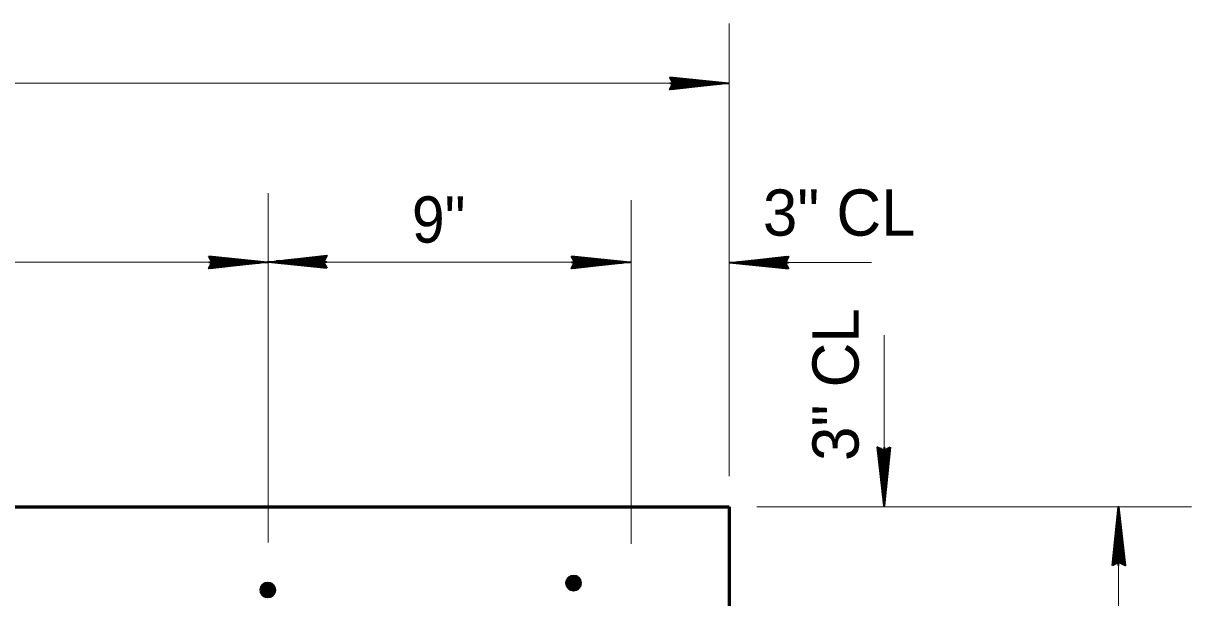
# Model space of a CAD drawing. Extents: x 4.49 to 7.69, y 0.28 to 2.27.
# Drawn here: x 5.3295 to 5.54, y 1.4617 to 1.5652 of the extents above; entities that cross this region are included whole.
import ezdxf
from ezdxf.enums import TextEntityAlignment as Align

# ---------------------------------------------------------------- set-up
doc = ezdxf.new("R2010")
doc.units = 0
doc.header["$LTSCALE"] = 0.0033
doc.layers.add('1', color=7, linetype='Continuous', lineweight=35)

msp = doc.modelspace()

# ---------------------------------------------------------------- linework, layer by layer
at = {"layer": '1', "lineweight": 13}
for p, q in [((5.456667, 1.483583), (5.456667, 1.565167)), ((4.87325, 1.554417), (5.455583, 1.554417)), ((5.373583, 1.471667), (5.373583, 1.534583)), ((5.439, 1.471417), (5.439, 1.533333)), ((4.89, 1.522167), (5.436917, 1.522167)), ((5.466583, 1.522083), (5.482333, 1.522083)), ((5.484583, 1.488167), (5.484583, 1.509)), ((5.461667, 1.478083), (5.54, 1.478083)), ((5.526833, 1.477417), (5.526833, 1.311417))]:
    msp.add_line(p, q, dxfattribs=at)
at = {"layer": '1'}
for p, q in [((5.446, 1.554417), (5.456583, 1.554417)), ((5.446167, 1.55375), (5.4535, 1.5545)), ((5.44625, 1.555417), (5.454083, 1.5545)), ((5.44625, 1.555417), (5.454083, 1.5545)), ((5.44625, 1.555333), (5.454083, 1.5545)), ((5.44625, 1.55525), (5.454083, 1.554417)), ((5.44625, 1.55525), (5.454083, 1.55425)), ((5.44625, 1.553583), (5.453583, 1.554417)), ((5.44625, 1.5535), (5.453583, 1.55425)), ((5.44625, 1.553333), (5.453583, 1.554167)), ((5.362917, 1.522167), (5.3735, 1.522167)), ((5.363083, 1.5215), (5.370417, 1.52225)), ((5.363167, 1.523167), (5.371, 1.52225)), ((5.363167, 1.523167), (5.371, 1.52225)), ((5.363167, 1.523083), (5.371, 1.52225)), ((5.363167, 1.523), (5.371, 1.522167)), ((5.363167, 1.523), (5.371, 1.522)), ((5.363167, 1.521333), (5.3705, 1.522167)), ((5.363167, 1.52125), (5.3705, 1.522)), ((5.384167, 1.522167), (5.373583, 1.522167)), ((5.383917, 1.521333), (5.376083, 1.522333)), ((5.383917, 1.521333), (5.376083, 1.522167)), ((5.383917, 1.521167), (5.376083, 1.522083)), ((5.383917, 1.521167), (5.376083, 1.522083)), ((5.383917, 1.52125), (5.376083, 1.522083)), ((5.383917, 1.52325), (5.376583, 1.522417)), ((5.383917, 1.523083), (5.376583, 1.522333)), ((5.383917, 1.523), (5.376583, 1.522167)), ((5.384, 1.522833), (5.376667, 1.522083)), ((5.42825, 1.522167), (5.438833, 1.522167)), ((5.428417, 1.5215), (5.43575, 1.52225)), ((5.4285, 1.523167), (5.436333, 1.52225)), ((5.4285, 1.523167), (5.436333, 1.52225)), ((5.4285, 1.523083), (5.436333, 1.52225)), ((5.4285, 1.523), (5.436333, 1.522167)), ((5.4285, 1.523), (5.436333, 1.522)), ((5.4285, 1.521333), (5.435833, 1.522167)), ((5.4285, 1.52125), (5.435833, 1.522)), ((5.467333, 1.522), (5.45675, 1.522)), ((5.467083, 1.521167), (5.45925, 1.522167)), ((5.467083, 1.521167), (5.45925, 1.522)), ((5.467083, 1.523083), (5.45975, 1.52225)), ((5.467083, 1.522917), (5.45975, 1.522167)), ((5.467083, 1.522833), (5.45975, 1.522)), ((5.467167, 1.522667), (5.459833, 1.521917)), ((5.363167, 1.521083), (5.3705, 1.521917)), ((5.4285, 1.521083), (5.435833, 1.521917)), ((5.467083, 1.521), (5.45925, 1.521917)), ((5.467083, 1.521), (5.45925, 1.521917)), ((5.467083, 1.521083), (5.45925, 1.521917)), ((5.4835, 1.488583), (5.484333, 1.48125)), ((5.483667, 1.488583), (5.484417, 1.48125)), ((5.48375, 1.488583), (5.484583, 1.48125)), ((5.483917, 1.488667), (5.484667, 1.481333)), ((5.485417, 1.488583), (5.484417, 1.48075)), ((5.484583, 1.488833), (5.484583, 1.47825)), ((5.485417, 1.488583), (5.484583, 1.48075)), ((5.485583, 1.488583), (5.484667, 1.48075)), ((5.485583, 1.488583), (5.484667, 1.48075)), ((5.4855, 1.488583), (5.484667, 1.48075)), ((5.526833, 1.4675), (5.526833, 1.478083)), ((5.525833, 1.46775), (5.52675, 1.475583)), ((5.525833, 1.46775), (5.52675, 1.475583)), ((5.525917, 1.46775), (5.52675, 1.475583)), ((5.526, 1.46775), (5.526833, 1.475583)), ((5.526, 1.46775), (5.527, 1.475583)), ((5.5275, 1.467667), (5.52675, 1.475)), ((5.527667, 1.46775), (5.526833, 1.475083)), ((5.52775, 1.46775), (5.527, 1.475083)), ((5.527917, 1.46775), (5.527083, 1.475083))]:
    msp.add_line(p, q, dxfattribs=at)
at = {"layer": '1', "lineweight": 60}
msp.add_line((4.873333, 1.478083), (5.456667, 1.478083), dxfattribs=at)
at = {"layer": '1', "lineweight": 40}
for p, q in [((5.428, 1.463167), (5.427667, 1.465167)), ((5.428083, 1.46325), (5.42775, 1.465167)), ((5.429333, 1.4655), (5.427833, 1.465417)), ((5.429333, 1.465333), (5.427833, 1.46525)), ((5.429333, 1.46525), (5.427833, 1.465167)), ((5.429333, 1.465167), (5.427833, 1.465083)), ((5.428167, 1.46325), (5.427833, 1.465167)), ((5.42825, 1.46325), (5.427917, 1.46525)), ((5.4285, 1.46325), (5.428083, 1.46525)), ((5.428667, 1.463333), (5.42825, 1.46525)), ((5.42875, 1.463333), (5.428333, 1.46525)), ((5.428833, 1.463333), (5.428417, 1.465333)), ((5.428917, 1.463333), (5.428583, 1.465333)), ((5.429, 1.463417), (5.428667, 1.465333)), ((5.429167, 1.463417), (5.42875, 1.465417)), ((5.42925, 1.463417), (5.428833, 1.465417)), ((5.429333, 1.463417), (5.429, 1.465417)), ((5.429417, 1.463417), (5.429083, 1.465417)), ((5.429583, 1.4635), (5.42925, 1.465417)), ((5.372583, 1.46225), (5.372917, 1.464167)), ((5.37275, 1.462167), (5.373083, 1.464167)), ((5.37275, 1.463167), (5.37425, 1.463083)), ((5.37275, 1.463083), (5.37425, 1.463)), ((5.372833, 1.46425), (5.374333, 1.464167)), ((5.372833, 1.462167), (5.373167, 1.464167)), ((5.372833, 1.464083), (5.374333, 1.464)), ((5.372833, 1.464), (5.374333, 1.463917)), ((5.372833, 1.463917), (5.374333, 1.463833)), ((5.372833, 1.463833), (5.374333, 1.46375)), ((5.372833, 1.46375), (5.374333, 1.463667)), ((5.372833, 1.463667), (5.374333, 1.463583)), ((5.372833, 1.463583), (5.374333, 1.4635)), ((5.372833, 1.463583), (5.374333, 1.4635)), ((5.372833, 1.4635), (5.374333, 1.463333)), ((5.372833, 1.463333), (5.374333, 1.463167)), ((5.372917, 1.462167), (5.373333, 1.464167)), ((5.373, 1.462167), (5.373417, 1.464167)), ((5.373167, 1.462167), (5.3735, 1.464083)), ((5.37325, 1.462083), (5.373583, 1.464083)), ((5.373333, 1.462083), (5.37375, 1.464083)), ((5.373417, 1.462083), (5.373833, 1.464)), ((5.3735, 1.462083), (5.373917, 1.464)), ((5.373667, 1.462), (5.374083, 1.464)), ((5.373917, 1.462), (5.37425, 1.464)), ((5.374, 1.462), (5.374333, 1.463917)), ((5.374083, 1.462), (5.374417, 1.463917)), ((5.374167, 1.461917), (5.3745, 1.463917)), ((5.429333, 1.465083), (5.427833, 1.465)), ((5.429333, 1.465), (5.427833, 1.464917)), ((5.429333, 1.464917), (5.427833, 1.464833)), ((5.429333, 1.464833), (5.427833, 1.46475)), ((5.429333, 1.464833), (5.427833, 1.46475)), ((5.429333, 1.46475), (5.427833, 1.464583)), ((5.429333, 1.464583), (5.427833, 1.464417)), ((5.429417, 1.464417), (5.427917, 1.464333)), ((5.429417, 1.464333), (5.427917, 1.46425)), ((5.429417, 1.46425), (5.427917, 1.464167)), ((5.429417, 1.464167), (5.427917, 1.464083)), ((5.429417, 1.464083), (5.427917, 1.464)), ((5.429417, 1.464), (5.427917, 1.463917)), ((5.429417, 1.463917), (5.427917, 1.463833)), ((5.429417, 1.46375), (5.427917, 1.463667)), ((5.429417, 1.463667), (5.427917, 1.463583)), ((5.429417, 1.463583), (5.427917, 1.4635)), ((5.429417, 1.4635), (5.427917, 1.463417)), ((5.429417, 1.463417), (5.427917, 1.463333)), ((5.37275, 1.463), (5.37425, 1.462917)), ((5.37275, 1.462917), (5.37425, 1.462833)), ((5.37275, 1.462833), (5.37425, 1.46275)), ((5.37275, 1.46275), (5.37425, 1.462667)), ((5.37275, 1.462667), (5.37425, 1.462583)), ((5.37275, 1.4625), (5.37425, 1.462417)), ((5.37275, 1.462417), (5.37425, 1.462333)), ((5.37275, 1.462333), (5.37425, 1.46225)), ((5.37275, 1.46225), (5.37425, 1.462167)), ((5.37275, 1.462167), (5.37425, 1.462083))]:
    msp.add_line(p, q, dxfattribs=at)
at = {"layer": '1'}
for points in [[(5.446, 1.5555), (5.456583, 1.554417), (5.446, 1.55325), (5.446583, 1.554417)], [(5.44675, 1.5545), (5.451417, 1.554583), (5.451417, 1.5545), (5.4505, 1.5545), (5.44675, 1.554583), (5.44975, 1.554667), (5.446583, 1.55475), (5.448833, 1.554833), (5.446583, 1.554917), (5.450083, 1.554667), (5.45475, 1.5545), (5.453833, 1.55425), (5.455083, 1.55425), (5.44675, 1.55425), (5.449167, 1.554083), (5.446583, 1.554083), (5.451917, 1.5545), (5.446583, 1.553833)], [(5.362917, 1.52325), (5.3735, 1.522167), (5.362917, 1.521), (5.3635, 1.522167)], [(5.363667, 1.52225), (5.368333, 1.522333), (5.368333, 1.52225), (5.367417, 1.52225), (5.363667, 1.522333), (5.366667, 1.522417), (5.3635, 1.5225), (5.36575, 1.522583), (5.3635, 1.522667), (5.367, 1.522417), (5.371667, 1.52225), (5.37075, 1.522), (5.372, 1.522), (5.363667, 1.522), (5.366083, 1.521833), (5.3635, 1.521833), (5.368833, 1.52225), (5.3635, 1.521583)], [(5.384167, 1.521083), (5.373583, 1.522167), (5.384167, 1.523333), (5.383583, 1.522167)], [(5.383417, 1.522083), (5.37875, 1.522), (5.37875, 1.522083), (5.379667, 1.522083), (5.383417, 1.522), (5.380417, 1.521917), (5.383583, 1.521833), (5.381333, 1.52175), (5.383583, 1.521667), (5.380083, 1.521917), (5.375417, 1.522083), (5.376333, 1.522333), (5.375083, 1.522333), (5.383417, 1.522333), (5.381, 1.5225), (5.383583, 1.5225), (5.37825, 1.522083), (5.383583, 1.52275)], [(5.42825, 1.52325), (5.438833, 1.522167), (5.42825, 1.521), (5.428833, 1.522167)], [(5.429, 1.52225), (5.433667, 1.522333), (5.433667, 1.52225), (5.43275, 1.52225), (5.429, 1.522333), (5.432, 1.522417), (5.428833, 1.5225), (5.431083, 1.522583), (5.428833, 1.522667), (5.432333, 1.522417), (5.437, 1.52225), (5.436083, 1.522), (5.437333, 1.522), (5.429, 1.522), (5.431417, 1.521833), (5.428833, 1.521833), (5.434167, 1.52225), (5.428833, 1.521583)], [(5.467333, 1.520917), (5.45675, 1.522), (5.467333, 1.523167), (5.46675, 1.522)], [(5.466583, 1.521917), (5.461917, 1.521833), (5.461917, 1.521917), (5.462833, 1.521917), (5.466583, 1.521833), (5.463583, 1.52175), (5.46675, 1.521667), (5.4645, 1.521583), (5.46675, 1.5215), (5.46325, 1.52175), (5.458583, 1.521917), (5.4595, 1.522167), (5.45825, 1.522167), (5.466583, 1.522167), (5.464167, 1.522333), (5.46675, 1.522333), (5.461417, 1.521917), (5.46675, 1.522583)], [(5.485667, 1.488833), (5.484583, 1.47825), (5.483417, 1.488833), (5.484583, 1.48825)], [(5.484667, 1.488083), (5.48475, 1.483417), (5.484667, 1.483417), (5.484667, 1.484333), (5.48475, 1.488083), (5.484833, 1.485083), (5.484917, 1.48825), (5.485, 1.486), (5.485083, 1.48825), (5.484833, 1.48475), (5.484667, 1.480083), (5.484417, 1.481), (5.484417, 1.47975), (5.484417, 1.488083), (5.48425, 1.485667), (5.48425, 1.48825), (5.484667, 1.482917), (5.484, 1.48825)], [(5.52575, 1.4675), (5.526833, 1.478083), (5.528, 1.4675), (5.526833, 1.468083)], [(5.52675, 1.46825), (5.526667, 1.472917), (5.52675, 1.472917), (5.52675, 1.472), (5.526667, 1.46825), (5.526583, 1.47125), (5.5265, 1.468083), (5.526417, 1.470333), (5.526333, 1.468083), (5.526583, 1.471583), (5.52675, 1.47625), (5.527, 1.475333), (5.527, 1.476583), (5.527, 1.46825), (5.527167, 1.470667), (5.527167, 1.468083), (5.52675, 1.473417), (5.527417, 1.468083)]]:
    msp.add_lwpolyline(points, close=True, dxfattribs=at)
for points in [[(5.44675, 1.5545), (5.446333, 1.55525), (5.446583, 1.555), (5.44675, 1.554667), (5.447, 1.55475), (5.446833, 1.555083), (5.446667, 1.554333), (5.4465, 1.553833), (5.44625, 1.553417)], [(5.363667, 1.52225), (5.36325, 1.523), (5.3635, 1.52275), (5.363667, 1.522417), (5.363917, 1.5225), (5.36375, 1.522833), (5.363583, 1.522083), (5.363417, 1.521583), (5.363167, 1.521167)], [(5.383417, 1.522083), (5.383833, 1.521333), (5.383583, 1.521583), (5.383417, 1.521917), (5.383167, 1.521833), (5.383333, 1.5215), (5.3835, 1.52225), (5.383667, 1.52275), (5.383917, 1.523167)], [(5.429, 1.52225), (5.428583, 1.523), (5.428833, 1.52275), (5.429, 1.522417), (5.42925, 1.5225), (5.429083, 1.522833), (5.428917, 1.522083), (5.42875, 1.521583), (5.4285, 1.521167)], [(5.466583, 1.521917), (5.467, 1.521167), (5.46675, 1.521417), (5.466583, 1.52175), (5.466333, 1.521667), (5.4665, 1.521333), (5.466667, 1.522083), (5.466833, 1.522583), (5.467083, 1.523)], [(5.484667, 1.488083), (5.485417, 1.4885), (5.485167, 1.48825), (5.484833, 1.488083), (5.484917, 1.487833), (5.48525, 1.488), (5.4845, 1.488167), (5.484, 1.488333), (5.483583, 1.488583)], [(5.52675, 1.46825), (5.526, 1.467833), (5.52625, 1.468083), (5.526583, 1.46825), (5.5265, 1.4685), (5.526167, 1.468333), (5.526917, 1.468167), (5.527417, 1.468), (5.527833, 1.46775)]]:
    msp.add_lwpolyline(points, dxfattribs=at)
at = {"layer": '1', "lineweight": 60}
msp.add_lwpolyline([(5.456667, 1.478083), (5.456667, 1.311417), (4.873333, 1.311417), (4.873333, 1.478083)], dxfattribs=at)
at = {"layer": '1', "lineweight": 40}
for points in [[(5.428583, 1.463), (5.428917, 1.465583), (5.429417, 1.46325), (5.428333, 1.465583), (5.427917, 1.463167), (5.427583, 1.465167), (5.429667, 1.465167), (5.427333, 1.46425), (5.429917, 1.4645), (5.427583, 1.4635), (5.429917, 1.463833), (5.427333, 1.464667), (5.429083, 1.463083), (5.42925, 1.4655), (5.427417, 1.463833), (5.429833, 1.464917), (5.429417, 1.46325), (5.427917, 1.463167), (5.427333, 1.46425), (5.427583, 1.465167), (5.428333, 1.465583), (5.42925, 1.4655), (5.429833, 1.464917), (5.42875, 1.46425), (5.427833, 1.465417), (5.427583, 1.4635), (5.42875, 1.46425), (5.42925, 1.463167), (5.429917, 1.464167), (5.428833, 1.46425), (5.427583, 1.465083), (5.428833, 1.463083), (5.429167, 1.464417), (5.429667, 1.465167)], [(5.373583, 1.46175), (5.37325, 1.464333), (5.37275, 1.462), (5.373833, 1.464333), (5.37425, 1.461917), (5.374583, 1.463917), (5.3725, 1.463917), (5.374833, 1.463), (5.37225, 1.46325), (5.374583, 1.46225), (5.37225, 1.462583), (5.374833, 1.463417), (5.373083, 1.461833), (5.372917, 1.46425), (5.37475, 1.462583), (5.372333, 1.463667), (5.37275, 1.462), (5.37425, 1.461917), (5.374833, 1.463), (5.374583, 1.463917), (5.373833, 1.464333), (5.372917, 1.46425), (5.372333, 1.463667), (5.373417, 1.463), (5.374333, 1.464167), (5.374583, 1.46225), (5.373417, 1.463), (5.372917, 1.461917), (5.37225, 1.462917), (5.373333, 1.463), (5.374583, 1.463833), (5.373333, 1.461833), (5.373, 1.463167), (5.3725, 1.463917)]]:
    msp.add_lwpolyline(points, dxfattribs=at)
for centre in [(5.428633, 1.464333), (5.373533, 1.463083)]:
    msp.add_circle(centre, 0.00132, dxfattribs=at)

# ---------------------------------------------------------------- texts
at = {"layer": '1'}
msp.add_text('3" CL', height=0.008334, dxfattribs=at).set_placement((5.46275, 1.526917))
at = {"layer": '1', "width": 0.95}
msp.add_text('9"', height=0.008334, dxfattribs=at).set_placement((5.404333, 1.525667), align=Align.CENTER)
at = {"layer": '1'}
msp.add_text('3" CL', height=0.008334, rotation=90, dxfattribs=at).set_placement((5.48, 1.486333))

doc.saveas('drawing.dxf')
